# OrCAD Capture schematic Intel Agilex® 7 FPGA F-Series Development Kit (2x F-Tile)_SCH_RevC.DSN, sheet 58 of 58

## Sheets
58 PG44 5V0, MAX: 2V5, 1V8, 1V2: size C
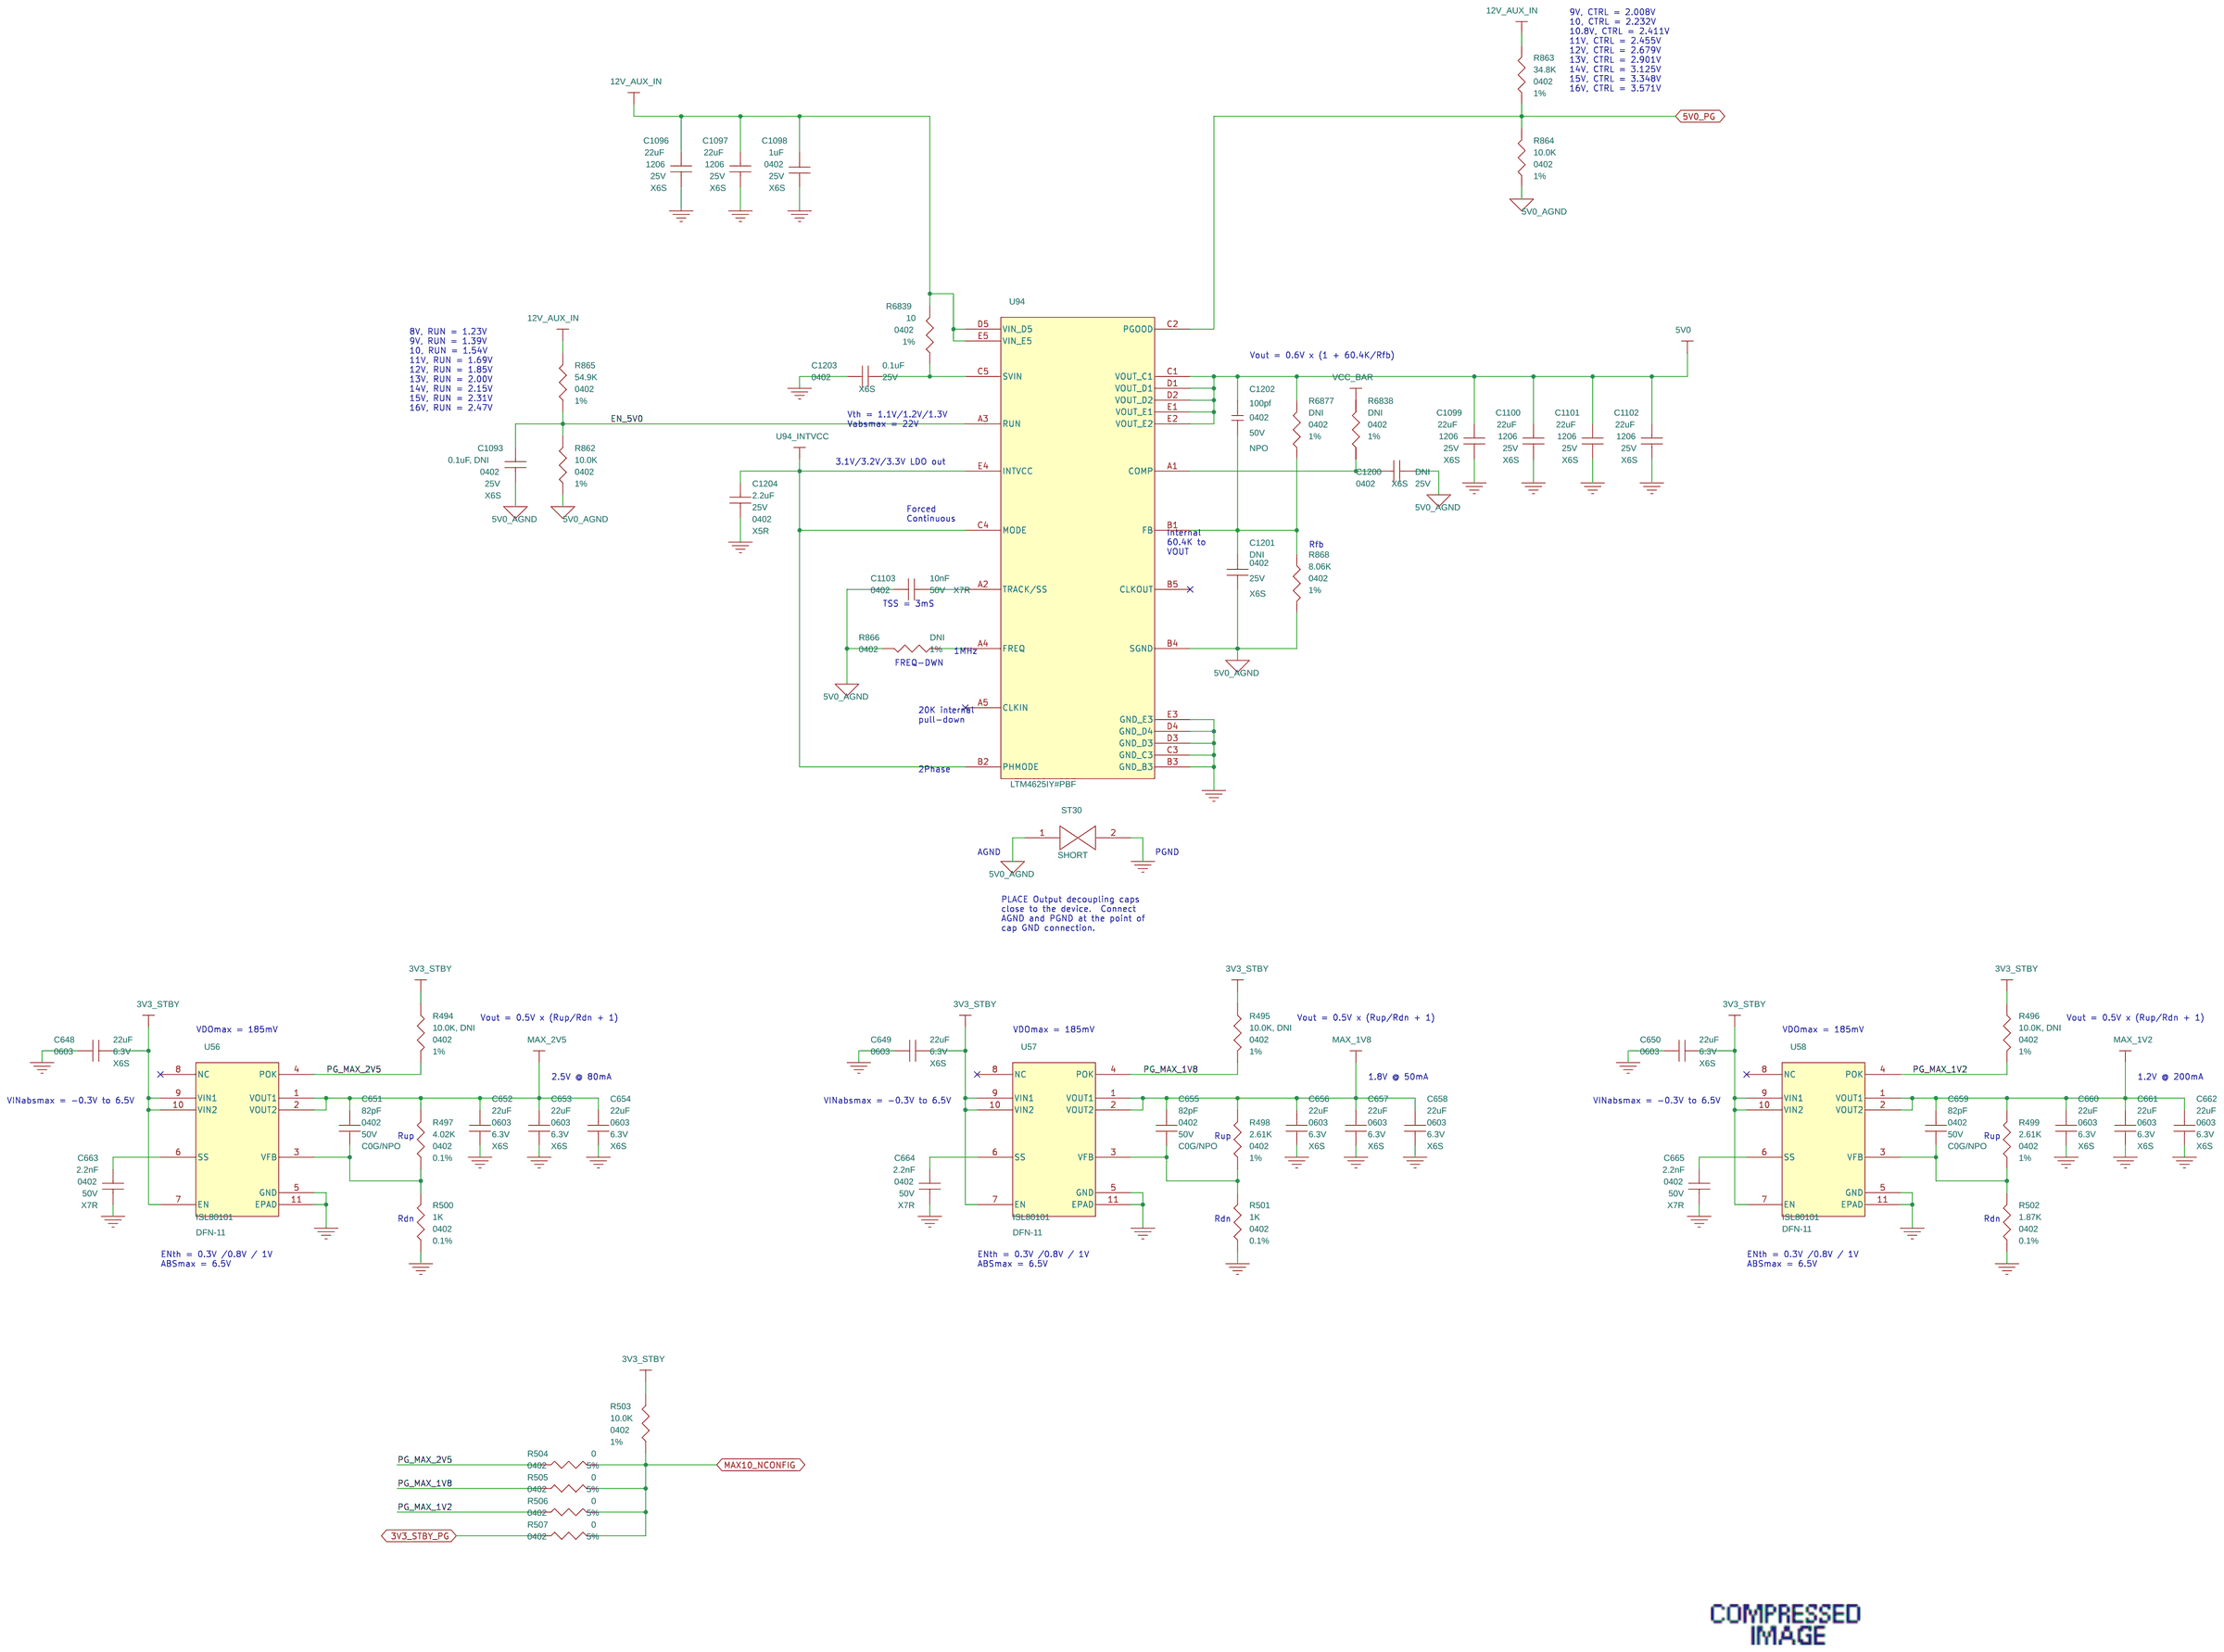
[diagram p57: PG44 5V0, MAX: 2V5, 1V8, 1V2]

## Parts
C648  22uF  [0603]
C649  22uF  [0603]
C650  22uF  [0603]
C651  82pF  [0402]
C652  22uF  [0603]
C653  22uF  [0603]
C654  22uF  [0603]
C655  82pF  [0402]
C656  22uF  [0603]
C657  22uF  [0603]
C658  22uF  [0603]
C659  82pF  [0402]
C660  22uF  [0603]
C661  22uF  [0603]
C662  22uF  [0603]
C663  2.2nF  [0402]
C664  2.2nF  [0402]
C665  2.2nF  [0402]
C1093  0.1uF, DNI  [0402]
C1096  22uF  [1206]
C1097  22uF  [1206]
C1098  1uF  [0402]
C1099  22uF  [1206]
C1100  22uF  [1206]
C1101  22uF  [1206]
C1102  22uF  [1206]
C1103  10nF  [0402]
C1200  DNI  [0402]
C1201  DNI  [0402]
C1202  100pf  [0402]
C1203  0.1uF  [0402]
C1204  2.2uF  [0402]
R494  10.0K, DNI  [0402]
R495  10.0K, DNI  [0402]
R496  10.0K, DNI  [0402]
R497  4.02K  [0402]
R498  2.61K  [0402]
R499  2.61K  [0402]
R500  1K  [0402]
R501  1K  [0402]
R502  1.87K  [0402]
R503  10.0K  [0402]
R504  0  [0402]
R505  0  [0402]
R506  0  [0402]
R507  0  [0402]
R862  10.0K  [0402]
R863  34.8K  [0402]
R864  10.0K  [0402]
R865  54.9K  [0402]
R866  DNI  [0402]
R868  8.06K  [0402]
R6838  DNI  [0402]
R6839  10  [0402]
R6877  DNI  [0402]
ST30  SHORT  [SHORT]
U56  ISL80101  [DFN-11]
U57  ISL80101  [DFN-11]
U58  ISL80101  [DFN-11]
U94  LTM4625IY#PBF  [BGA-25]

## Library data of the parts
C648-C650 C652-C654 C656-C658 C660-C662 = CAP: CAP CER 22UF 6.3V X6S 0603; AGILE_LINK: http://sj-agile9app/Agile/PLMServlet?action=OpenEmailObject&classid=10000&objid=257560276; Item Num: H63299-001; LIFECYCLE_PHASE: Active; Lead Free Status: Not Lead Free; MFR_LIFECYCLE: Active; Manufacturer: Murata; Manufacturer Part Num: GRM188C80J226ME15D; Num Pins: 2; PART_SUBCLASS: CAPACITORS; RATED_VOLTAGE: 6.3V; RoHS Compliant: RoHS Compliant; TOLERANCE: 20%; Temperature Coefficient: X6S
C651 C655 C659 = CAP: CAP CER 82PF 50V C0G/NPO 0402; Dielectric: C0G/NPO; Item Num: K13615-001; Lead Free Status: Yes; Manufacturer: Yageo; Manufacturer Part Num: CC0402JRNPO9BN820; Num Pins: 2; Part Class: CAPACITORS; RoHS Compliant: Yes; Temperature Coefficient: C0G/NPO; Tolerance: 5%; Voltage Rating: 50V
C663-C665 = CAP: CAP CER 2200PF 50V 10% X7R 0402; CAPACITANCE: 2200pF; Dielectric: X7R; Item Num: K13631-001; LIFECYCLE_PHASE: Active; Lead Free Status: Lead Free; Manufacturer: TDK; Manufacturer Part Num: CGJ2B2X7R1E222K050BA; Num Pins: 2; PART_SUBCLASS: CAPACITORS; Part Class: CAPACITORS; RATED_VOLTAGE: 50V; RoHS Compliant: RoHS Compliant; Temperature Coefficient: X7R; Tolerance: +/-10%
C1093 C1200 C1201 = CAP: CAP CER 0.1UF 25V X6S 0402; CAPACITANCE: 0.1uF; Dielectric: X6S; IPN: K19434-001; Item Num: K19434-001; LIFECYCLE_PHASE: Active; Lead Free Status: Lead Free; MFR_LIFECYCLE: Active; Manufacturer: Murata; Manufacturer Part Num: GRM155C81E104KA12D; Num Pins: 2; PART_SUBCLASS: CAPACITORS; Part Class: CAPACITORS; RATED_VOLTAGE: 25V; RoHS Compliant: RoHS Compliant; Temperature Coefficient: X6S; Tolerance: 10%
C1096 C1097 C1099-C1102 = CAP: CAP CER 22UF 25V X6S 1206; AGILE_LINK: http://sj-agile9app/Agile/PLMServlet?action=OpenEmailObject&classid=10000&objid=257560276; Item Num: H65936-001; LIFECYCLE_PHASE: Active; Lead Free Status: Lead Free; MFR_LIFECYCLE: Active; Manufacturer: Murata; Manufacturer Part Num: GRM31CC81E226KE11L; Num Pins: 2; PART_SUBCLASS: CAPACITORS; RATED_VOLTAGE: 25V; RoHS Compliant: RoHS Compliant; TOLERANCE: 10%; Thermal Coefficient: X6S
C1098 = CAP: CAP CER 1UF 25V X6S 0402; Item Num: H81594-001; Lead Free Status: Yes; Manufacturer: Murata; Manufacturer Part Num: GRM155C81E105KE11D; Num Pins: 2; Part Class: CAPACITORS; RATED_VOLTAGE: 25V; RoHS Compliant: Yes; Temperature Coefficient: X6S
C1103 = Cap_10000PF_50V_0402: CAP - CER, 10NF, 50V, +/-10%, X7R, 0402 SMD; Dielectric: X7R; Item Num: H61346-001; LIFECYCLE_PHASE: Active; Lead Free Status: Lead Free; Manufacturer Part Num: GRM155R71H103KA88D; Num Pins: 2; Part Class: CAPACITORS; RATED_VOLTAGE: 50V; RoHS Compliant: RoHS Compliant; Temperature Coefficient: X7R; Tolerance: 10%; Voltage: 50V
C1202 = Cap,_NP,_0402: CAP, CERAMIC, 100pF, 0402, 5%, 50VDC, NPO; Item Num: K13768-001; Manufacturer: Murata; Manufacturer Part Num: GRM1555C1H101JA01D; Temperature Coefficient: NPO; Voltage: 50V
C1203 = CAP: CAP CER 0.1UF 25V X6S 0402; Dielectric: X6S; IPN: K19434-001; Item Num: K19434-001; LIFECYCLE_PHASE: Active; Lead Free Status: Lead Free; MFR_LIFECYCLE: Active; Manufacturer: Murata; Manufacturer Part Num: GRM155C81E104KA12D; Num Pins: 2; PART_SUBCLASS: CAPACITORS; Part Class: CAPACITORS; RATED_VOLTAGE: 25V; RoHS Compliant: RoHS Compliant; Temperature Coefficient: X6S; Tolerance: 10%
C1204 = CAP: CAPC,X5R,0402,2.2UF,25.00V,+/- 10%; CLASS: DISCRETE; Dielectric Type: X5R; FPLIST: CC0805N,CC0805L,CC0805M; IPN: H87713-001; Item Num: H87713-001; Manufacturer: Murata; Manufacturer PN: GRM155R61E225KE11D; Manufacturer Part Num: GRM155R61E225KE11D; PART_NUMBER: 150-0578; Rated Voltage: 25V; Temperature Coefficient: X5R; Tolerance: 10%
R494-R496 R866 R6838 R6877 = RESISTOR: RES,10.0K OHMS,1.0%,1/16W, 0402; AGILE_LINK: http://sj-agile9app/Agile/PLMServlet?action=OpenEmailObject&classid=10000&objid=146548997; Item Num: K28115-001; LIFECYCLE_PHASE: Active; Lead Free Status: Yes; MFR_LIFECYCLE: Active; Manufacturer: Panasonic; Manufacturer Part Num: ERJ-2RKF1002X; Num Pins: 2; PART_SUBCLASS: RESISTORS; POWER: 1/16W; RESISTANCE: 10.0K; RoHS Compliant: Yes; TOLERANCE: 1%
R497 = RESISTOR: RES SMD 4.02KOHM 0.1% 1/16W 0402; Item Num: K21642-001; Lead Free Status: Yes; Manufacturer: Panasonic; Manufacturer Part Num: ERA-2AEB4021X; Num Pins: 2; Part Class: RESISTORS; RoHS Compliant: Yes; TOLERANCE: 0.1%
R498 R499 = RESISTOR: RES SMD 2.61K 1% 1/16W 0402; Item Num: A93548-419; Lead Free Status: Yes; Manufacturer: RC0402FR-072K61L; Manufaturer: Yageo; Num Pins: 2; Part Class: RESISTORS; RoHS Compliant: Yes; TOLERANCE: 1%
R500 R501 = RESISTOR: RES SMD 1K OHM 0.1% 1/16W 0402; Item Num: K21643-001; Lead Free Status: Yes; Manufacturer: Panasonic; Manufacturer Part Num: ERA-2AEB102X; Num Pins: 2; Part Class: Resistors; Power Rating: 1/16W; RoHS Compliant: Yes; TOLERANCE: 0.1%
R502 = RESISTOR: RES 0402 1.87K 0.1% 1/16W 0402; Item Num: K34571-001; Lead Free Status: Yes; Manufacturer: Panasonic; Manufacturer Part Num: ERA-2AEB1871X; Manufaturer: Panasonic; Num Pins: 2; Part Class: Resistors; TOLERANCE: 0.1%
R503 R862 R864 = RESISTOR: RES,10.0K OHMS,1.0%,1/16W, 0402; AGILE_LINK: http://sj-agile9app/Agile/PLMServlet?action=OpenEmailObject&classid=10000&objid=146548997; Item Num: K28115-001; LIFECYCLE_PHASE: Active; Lead Free Status: Yes; MFR_LIFECYCLE: Active; Manufacturer: Panasonic; Manufacturer Part Num: ERJ-2RKF1002X; Num Pins: 2; PART_SUBCLASS: RESISTORS; POWER: 1/16W; RoHS Compliant: Yes; TOLERANCE: 1%
R504-R507 = RESISTOR: RES ZERO OHM 1/16W 5% 0402 SMD; Item Num: A93549-001; Lead Free Status: No; Manufacturer: Yageo; Manufacturer Part Num: RC0402JR-070RL; Num Pins: 2; Part Class: RESISTORS; RoHS Compliant: Yes; Tolerance: 5%
R863 = RESISTOR: RES - 34.8K OHM, 1/10W, 1%, 0402 SMD; AGILE_LINK: http://sj-agile9app/Agile/PLMServlet?action=OpenEmailObject&classid=10000&objid=146548997; Item Num: C94374-001; LIFECYCLE_PHASE: Active; Lead Free Status: Yes; MFR_LIFECYCLE: Active; Manufacturer: Panasonic; Manufacturer Part Num: ERJ-2RKF3482X; Num Pins: 2; PART_SUBCLASS: RESISTORS; POWER: 1/16W; RoHS Compliant: Yes; TOLERANCE: 1%
R865 = RESISTOR: RES SMD 54.9K OHM 1% 1/10W 0402; AGILE_LINK: http://sj-agile9app/Agile/PLMServlet?action=OpenEmailObject&classid=10000&objid=146548997; Item Num: K12137-001; LIFECYCLE_PHASE: Active; Lead Free Status: Yes; MFR_LIFECYCLE: Active; Manufacturer: Panasonic; Manufacturer Part Num: ERJ-2RKF5492X; Num Pins: 2; PART_SUBCLASS: RESISTORS; POWER: 1/10W; RoHS Compliant: Yes; TOLERANCE: 1%
R868 = RESISTOR: RES,8.06K OHMS,1.0%,1/16W, 0402; AGILE_LINK: http://sj-agile9app/Agile/PLMServlet?action=OpenEmailObject&classid=10000&objid=146548997; Item Num: H30877-001; LIFECYCLE_PHASE: Active; Lead Free Status: Yes; MFR_LIFECYCLE: Active; Manufacturer: Panasonic; Manufacturer Part Num: ERJ-2RKF8061X; Num Pins: 2; PART_SUBCLASS: RESISTORS; POWER: 1/16W; RoHS Compliant: Yes; TOLERANCE: 1%
R6839 = RESISTOR: RES, 10 OHM, 1%, 1/16W, 0402; Item Num: A80345-001; LIFECYCLE_PHASE: Active; Lead Free Status: Yes; Manufacturer: Panasonic; Manufacturer Part Num: ERJ-2RKF10R0X; Num Pins: 2; PART_SUBCLASS: RESISTORS; POWER: 1/16W; Part Class: Resistors; RoHS Compliant: Yes; TOLERANCE: 1%
ST30 = SHORT
U56-U58 = EY1501di-adj: IC, Linear Regulator, 1A; Item Num: E81353-001; Manufacturer: Intel/Enpirion; Manufacturer Part Num: EY1501DI-ADJ
U94 = LTM4625IY#PBF: Module, Regulator, 20Vin, 5A Step-down, DC/DC; Item Num: M59346-001; Manufacturer: ADI

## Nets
3V3_STBY: C648.1 C649.1 C650.1 R494.1 R495.1 R496.1 R503.1 U56.7(EN) U56.9(VIN1) U56.10(VIN2) U57.7(EN) U57.9(VIN1) U57.10(VIN2) U58.7(EN) U58.9(VIN1) U58.10(VIN2) ; also on sheet 8 10 16 22 28 32 34 36 37 38 40 41 48 49 50 51 52 53 54
3V3_STBY_PG: R507.1 ; also on sheet 41
5V0: C1099.1 C1100.1 C1101.1 C1102.1 C1202.1 R6877.1 U94.C1(VOUT) U94.D1(VOUT) U94.D2(VOUT) U94.E1(VOUT) U94.E2(VOUT) ; also on sheet 36 43 44 45 46 47
5V0_AGND: C1093.2 C1103.1 C1200.2 C1201.1 R862.2 R864.2 R866.1 R868.1 ST30.1 U94.B4(SGND)
5V0_PG: R863.2 R864.1 U94.C2(PGOOD) ; also on sheet 41
12V_AUX_IN: C1096.1 C1097.1 C1098.2 R863.1 R865.1 R6839.2 U94.D5(VIN) U94.E5(VIN) ; also on sheet 10 40 42 43 44 45 46
GND: C648.2 C649.2 C650.2 C652.1 C653.1 C654.1 C656.1 C657.1 C658.1 C660.1 C661.1 C662.1 C663.2 C664.2 C665.2 C1096.2 C1097.2 C1098.1 C1099.2 C1100.2 C1101.2 C1102.2 C1203.2 C1204.2 R500.2 R501.2 R502.2 ST30.2 U56.5(GND) U56.11(EPAD) U57.5(GND) U57.11(EPAD) U58.5(GND) U58.11(EPAD) U94.B3(GND) U94.C3(GND) U94.D3(GND) U94.D4(GND) U94.E3(GND) ; also on sheet 8 9 10 11 12 13 15 16 19 20 21 22 23 24 25 26 27 28 29 30 31 32 33 34 35 36 37 38 39 40 41 42 43 44 45 46 47 48 49 50 51 52 53 54 55 56
EN_5V0: C1093.1 R862.1 R865.2 U94.A3(RUN)
MAX10_NCONFIG: R503.2 R504.2 R505.2 R506.2 R507.2 ; also on sheet 10
MAX_1V2: C659.2 C660.2 C661.2 C662.2 R499.2 U58.1(VOUT1) U58.2(VOUT2) ; also on sheet 10
MAX_1V8: C655.2 C656.2 C657.2 C658.2 R498.2 U57.1(VOUT1) U57.2(VOUT2) ; also on sheet 9 10 11 34
MAX_2V5: C651.2 C652.2 C653.2 C654.2 R497.2 U56.1(VOUT1) U56.2(VOUT2) ; also on sheet 10
PG_MAX_1V2: R496.2 R506.1 U58.4(POK)
PG_MAX_1V8: R495.2 R505.1 U57.4(POK)
PG_MAX_2V5: R494.2 R504.1 U56.4(POK)
U94_INTVCC: C1204.1 R6838.1 U94.B2(PHMODE) U94.C4(MODE) U94.E4(INTVCC)
N1532849: C651.1 R497.1 R500.1 U56.3(VFB)
N1532865: C663.1 U56.6(SS)
N1534404: C655.1 R498.1 R501.1 U57.3(VFB)
N1534420: C664.1 U57.6(SS)
N1535970: C659.1 R499.1 R502.1 U58.3(VFB)
N1535986: C665.1 U58.6(SS)
N6310318: C1103.2 U94.A2(TRACK/SS)
N6310354: C1201.2 C1202.2 R868.2 R6877.2 U94.B1(FB)
N6310567: R866.2 U94.A4(FREQ)
N6843686: C1200.1 R6838.2 U94.A1(COMP)
N6844906: C1203.1 R6839.1 U94.C5(SVIN)

Not connected (* = marked no-connect by the designer): U56 8(NC)*; U57 8(NC)*; U58 8(NC)*; U94 A5(CLKIN)* B5(CLKOUT)*

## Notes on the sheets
sheet 58
- 9V, CTRL = 2.008V
  10, CTRL = 2.232V
  10.8V, CTRL = 2.411V
  11V, CTRL = 2.455V
  12V, CTRL = 2.679V
  13V, CTRL = 2.901V
  14V, CTRL = 3.125V
  15V, CTRL = 3.348V
  16V, CTRL = 3.571V
- 8V, RUN = 1.23V
  9V, RUN = 1.39V
  10, RUN = 1.54V
  11V, RUN = 1.69V
  12V, RUN = 1.85V
  13V, RUN = 2.00V
  14V, RUN = 2.15V
  15V, RUN = 2.31V
  16V, RUN = 2.47V
- Vout = 0.6V x (1 + 60.4K/Rfb)
- Vth = 1.1V/1.2V/1.3V
  Vabsmax = 22V
- 3.1V/3.2V/3.3V LDO out
- Forced
  Continuous
- Internal
  60.4K to
  VOUT
- Rfb
- TSS = 3mS
- 1MHz
- FREQ-DWN
- 20K internal
  pull-down
- 2Phase
- AGND
- PGND
- PLACE Output decoupling caps
  close to the device.  Connect
  AGND and PGND at the point of
  cap GND connection.
- VDOmax = 185mV
- Vout = 0.5V x (Rup/Rdn + 1)
- VDOmax = 185mV
- Vout = 0.5V x (Rup/Rdn + 1)
- VDOmax = 185mV
- Vout = 0.5V x (Rup/Rdn + 1)
- 2.5V @ 80mA
- 1.8V @ 50mA
- 1.2V @ 200mA
- VINabsmax = -0.3V to 6.5V
- VINabsmax = -0.3V to 6.5V
- VINabsmax = -0.3V to 6.5V
- Rup
- Rup
- Rup
- Rdn
- Rdn
- Rdn
- ENth = 0.3V /0.8V / 1V
  ABSmax = 6.5V
- ENth = 0.3V /0.8V / 1V
  ABSmax = 6.5V
- ENth = 0.3V /0.8V / 1V
  ABSmax = 6.5V
